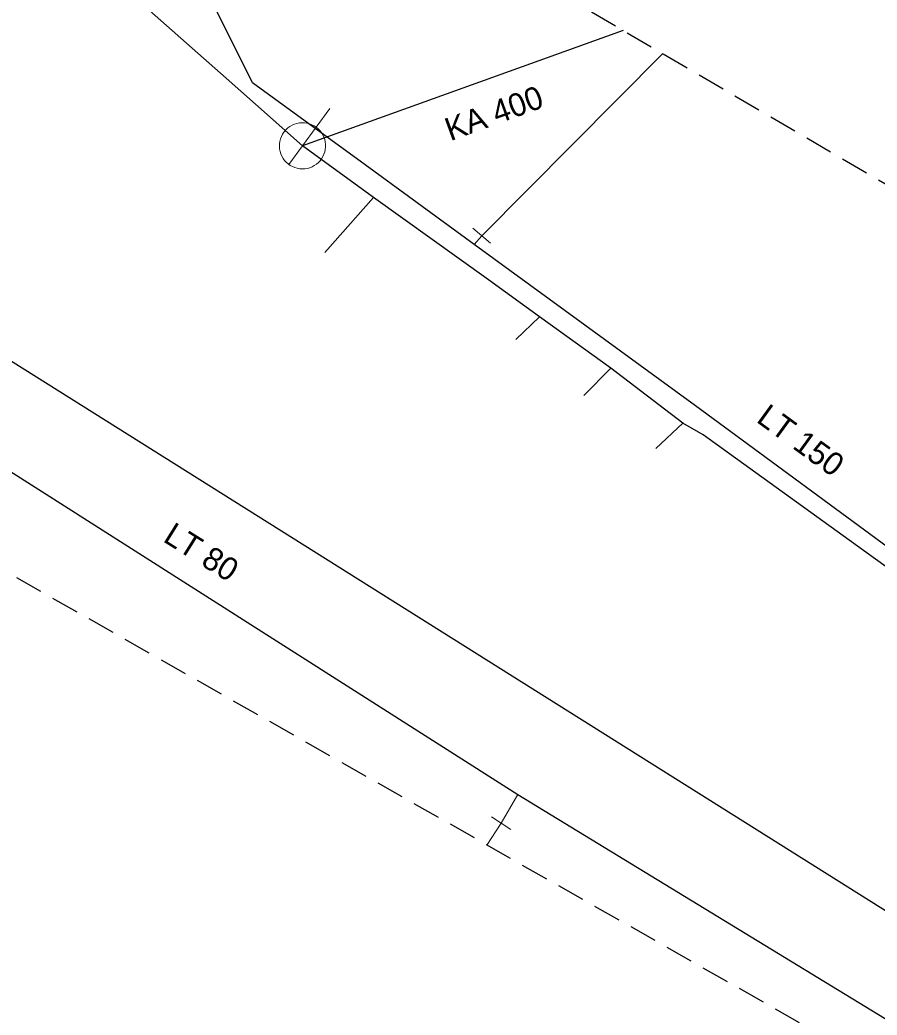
# Model space of a CAD drawing. Extents: x -747112 to -746911, y -964685 to -964545.
# Drawn here: x -747049.87 to -747012.74, y -964629.26 to -964586.15 of the extents above; entities that cross this region are included whole.
import ezdxf

# ---------------------------------------------------------------- set-up
doc = ezdxf.new("R2010")
doc.units = 0
doc.header["$LTSCALE"] = 0.4
doc.linetypes.add('MEDIUM_DASHED', pattern=[4.5, 3, -1.5])
doc.layers.add('1', color=7, linetype='Continuous')
for name, color, linetype, lineweight in [('11', 7, 'Continuous', 13), ('13', 7, 'Continuous', 13), ('14', 7, 'Continuous', 13), ('17', 7, 'Continuous', 25), ('22', 7, 'Continuous', 13), ('34', 7, 'Continuous', 13), ('63', 7, 'MEDIUM_DASHED', 25)]:
    doc.layers.add(name, color=color, linetype=linetype, lineweight=lineweight)

msp = doc.modelspace()

# ---------------------------------------------------------------- linework, layer by layer
at = {"layer": '11'}
for p, q in [((-747036.657, -964596.225), (-747034.561, -964593.842)), ((-747028.396, -964599.984), (-747027.37, -964599.01)), ((-747025.447, -964602.41), (-747024.27, -964601.239)), ((-747022.322, -964604.715), (-747021.16, -964603.609))]:
    msp.add_line(p, q, dxfattribs=at)
at = {"layer": '13'}
for p, q in [((-747022.027, -964587.606), (-747029.87, -964595.495)), ((-747028.302, -964619.701), (-747029.026, -964620.94)), ((-747029.026, -964620.94), (-747029.642, -964621.891))]:
    msp.add_line(p, q, dxfattribs=at)
at = {"layer": '14', "lineweight": 25}
msp.add_line((-747023.748, -964586.6), (-747037.631, -964591.6), dxfattribs=at)
at = {"layer": '14'}
msp.add_line((-747030.192, -964595.879), (-747029.87, -964595.495), dxfattribs=at)
at = {"layer": '14', "lineweight": 25}
for points in [[(-747037.631, -964591.6), (-747040.938, -964588.675), (-747049.3, -964581.28), (-747052.956, -964578.054), (-747060.077, -964571.761), (-747064.767, -964567.616), (-747073.861, -964559.579)], [(-746987.381, -964627.86), (-746994.138, -964622.982), (-747008.407, -964612.686), (-747020.272, -964604.125), (-747021.16, -964603.609), (-747024.27, -964601.239), (-747027.37, -964599.01), (-747029.581, -964597.407), (-747034.561, -964593.842), (-747037.631, -964591.6)]]:
    msp.add_lwpolyline(points, dxfattribs=at)
at = {"layer": '17'}
for points in [[(-746992.592, -964623.377), (-747002.848, -964615.868), (-747011.265, -964609.743), (-747020.612, -964602.861), (-747030.192, -964595.879), (-747034.92, -964592.421), (-747039.8, -964588.87), (-747041.949, -964584.539), (-747049.208, -964579.357)], [(-747058.793, -964595.589), (-747057.25, -964596.522), (-746948.662, -964664.784), (-746947.539, -964668.56)], [(-747055.973, -964602.077), (-747028.302, -964619.701), (-747009.793, -964630.991), (-746994.776, -964640.041), (-746974.873, -964652.184), (-746964.215, -964659.081)]]:
    msp.add_lwpolyline(points, dxfattribs=at)
at = {"layer": '22'}
msp.add_line((-747036.451, -964589.984), (-747038.22, -964592.407), dxfattribs=at)
msp.add_lwpolyline([(-747038.438, -964591.009), (-747038.497, -964591.101), (-747038.546, -964591.199), (-747038.585, -964591.302), (-747038.612, -964591.407), (-747038.627, -964591.516), (-747038.63, -964591.625), (-747038.621, -964591.735), (-747038.6, -964591.842), (-747038.568, -964591.947), (-747038.524, -964592.047), (-747038.47, -964592.142), (-747038.405, -964592.231), (-747038.331, -964592.312), (-747038.249, -964592.384), (-747038.159, -964592.447), (-747038.064, -964592.5), (-747037.963, -964592.543), (-747037.858, -964592.573), (-747037.75, -964592.592), (-747037.641, -964592.599), (-747037.531, -964592.594), (-747037.423, -964592.577), (-747037.317, -964592.549), (-747037.215, -964592.509), (-747037.118, -964592.458), (-747037.028, -964592.397), (-747036.944, -964592.326), (-747036.869, -964592.247), (-747036.802, -964592.159), (-747036.746, -964592.065), (-747036.7, -964591.966), (-747036.666, -964591.862), (-747036.643, -964591.756), (-747036.631, -964591.647), (-747036.632, -964591.537), (-747036.645, -964591.428), (-747036.669, -964591.321), (-747036.706, -964591.218), (-747036.752, -964591.119), (-747036.811, -964591.026), (-747036.878, -964590.94), (-747036.954, -964590.862), (-747037.04, -964590.792), (-747037.131, -964590.733), (-747037.229, -964590.684), (-747037.331, -964590.645), (-747037.437, -964590.618), (-747037.546, -964590.603), (-747037.656, -964590.6), (-747037.765, -964590.608), (-747037.872, -964590.629), (-747037.977, -964590.661), (-747038.077, -964590.704), (-747038.172, -964590.759), (-747038.261, -964590.823), (-747038.342, -964590.897), (-747038.415, -964590.979)], close=True, dxfattribs=at)
at = {"layer": '34'}
for p, q in [((-747030.253, -964595.174), (-747029.487, -964595.816)), ((-747029.445, -964620.668), (-747028.606, -964621.212))]:
    msp.add_line(p, q, dxfattribs=at)
at = {"layer": '63'}
msp.add_lwpolyline([(-746919.076, -964684.739), (-747112.263, -964574.928), (-747112.265, -964574.927), (-747112.266, -964574.925), (-747112.267, -964574.924), (-747112.268, -964574.922), (-747112.268, -964574.92), (-747112.268, -964574.918), (-747112.268, -964574.916), (-747112.267, -964574.914), (-747097.677, -964549.903), (-747095.061, -964544.933), (-747095.059, -964544.931), (-747095.058, -964544.93), (-747095.056, -964544.929), (-747095.054, -964544.928), (-747095.052, -964544.928), (-747095.05, -964544.928), (-747095.048, -964544.928), (-747095.047, -964544.929), (-746965.47, -964620.662)], dxfattribs=at)

# ---------------------------------------------------------------- texts
at = {"layer": '1'}
for s, rotation, p in [('KA 400', 20, (-747031.23, -964591.404)), ('LT 150', 324, (-747018.02, -964603.534)), ('LT 80 ', 328, (-747043.717, -964608.714))]:
    msp.add_text(s, height=1, rotation=rotation, dxfattribs=at).set_placement(p)

doc.saveas('drawing.dxf')
